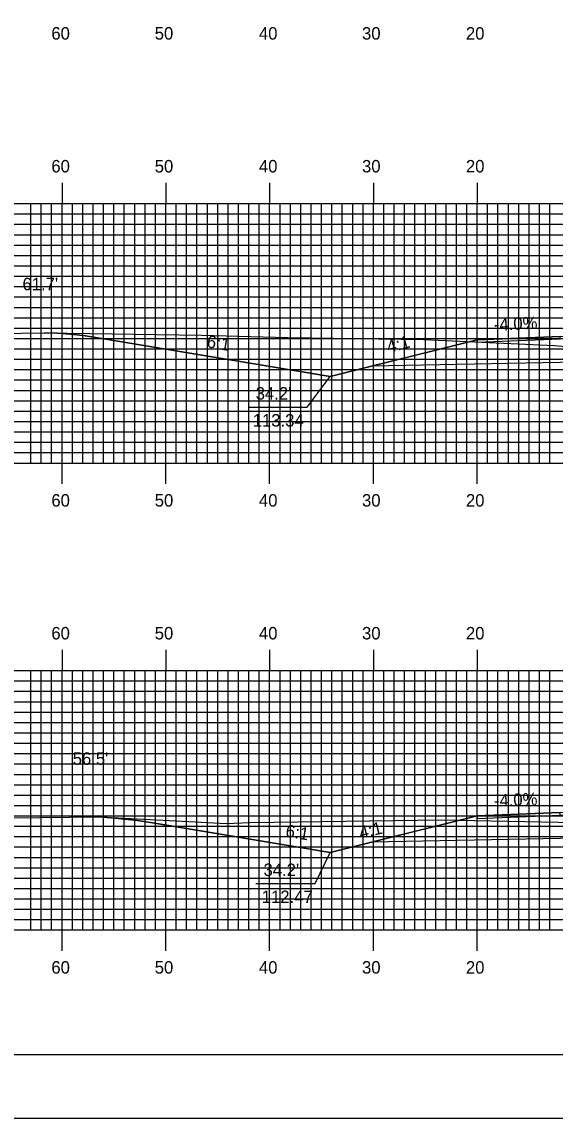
# Model space of a CAD drawing. Extents: x 1780286 to 1780629, y 442591 to 442811.
# Drawn here: x 1780388 to 1780439.4, y 442590.5 to 442696.2 of the extents above; entities that cross this region are included whole.
import ezdxf

# ---------------------------------------------------------------- set-up
doc = ezdxf.new("R2010")
doc.units = 0
for name, color, linetype in [('ANNOTATION', 7, 'Continuous'), ('BORDER', 7, 'Continuous'), ('D_Roadway_Centerline', 7, 'Continuous'), ('D_Roadway_Edge_Shoulder', 7, 'Continuous'), ('D_Roadway_SlopeLines', 7, 'Continuous'), ('D_Roadway_SubGrade', 7, 'Continuous'), ('D_Text_Standard', 7, 'Continuous'), ('H_V ANNOTATION', 7, 'Continuous'), ('MAJOR', 7, 'Continuous'), ('MINOR', 7, 'Continuous'), ('PLOT BOUNDARY', 7, 'Continuous'), ('S_Roadway_Centerline', 7, 'Continuous')]:
    doc.layers.add(name, color=color, linetype=linetype)

msp = doc.modelspace()

# ---------------------------------------------------------------- linework, layer by layer
at = {"layer": 'ANNOTATION'}
for points in [[(1780409.8, 442659.05), (1780415.49, 442659.05), (1780417.69, 442662.01)], [(1780410.55, 442613.15), (1780416.24, 442613.15), (1780417.69, 442616.13)]]:
    msp.add_lwpolyline(points, dxfattribs=at)
at = {"layer": 'BORDER'}
msp.add_lwpolyline([(1780302.27, 442596.67), (1780622.27, 442596.67), (1780622.27, 442806.67), (1780302.27, 442806.67)], close=True, dxfattribs=at)
at = {"layer": 'D_Roadway_Centerline'}
for points in [[(1780390.14, 442666.22), (1780391.39, 442666.18), (1780392.64, 442666.09), (1780393.89, 442665.95), (1780395.14, 442665.77), (1780417.69, 442662.01), (1780421.69, 442663.01), (1780431.87, 442665.55), (1780439.87, 442665.87), (1780451.87, 442666.11), (1780463.87, 442665.87), (1780471.87, 442665.55), (1780482.04, 442663.01), (1780486.04, 442662.01), (1780493.57, 442663.26), (1780494.82, 442663.44), (1780496.07, 442663.55), (1780497.32, 442663.59), (1780498.57, 442663.57)], [(1780395.38, 442619.56), (1780396.63, 442619.48), (1780397.88, 442619.36), (1780399.13, 442619.21), (1780400.38, 442619.02), (1780417.69, 442616.13), (1780421.69, 442617.13), (1780431.87, 442619.68), (1780439.87, 442620), (1780451.87, 442620.24), (1780463.87, 442620), (1780471.87, 442619.68), (1780482.04, 442617.13), (1780486.04, 442616.13), (1780490.6, 442616.89), (1780491.85, 442617.07), (1780493.1, 442617.19), (1780494.35, 442617.24), (1780495.6, 442617.23)]]:
    msp.add_lwpolyline(points, dxfattribs=at)
at = {"layer": 'D_Roadway_Edge_Shoulder'}
for points in [[(1780439.87, 442665.87), (1780431.87, 442665.55), (1780431.87, 442665.3), (1780439.87, 442665.62)], [(1780439.87, 442620), (1780431.87, 442619.68), (1780431.87, 442619.43), (1780439.87, 442619.75)]]:
    msp.add_lwpolyline(points, close=True, dxfattribs=at)
at = {"layer": 'D_Roadway_SlopeLines'}
for points in [[(1780417.69, 442662.01), (1780395.14, 442665.77), (1780393.89, 442665.95), (1780392.64, 442666.09), (1780391.39, 442666.18), (1780390.14, 442666.22)], [(1780431.87, 442665.55), (1780417.69, 442662.01)], [(1780417.69, 442616.13), (1780400.38, 442619.02), (1780399.13, 442619.21), (1780397.88, 442619.36), (1780396.63, 442619.48), (1780395.38, 442619.56)], [(1780431.87, 442619.68), (1780417.69, 442616.13)]]:
    msp.add_lwpolyline(points, dxfattribs=at)
at = {"layer": 'D_Roadway_SubGrade'}
for points in [[(1780439.87, 442663.37), (1780421.69, 442663.01), (1780431.87, 442665.55), (1780431.87, 442665.3), (1780439.87, 442665.62), (1780451.87, 442665.86), (1780463.87, 442665.62), (1780471.87, 442665.3), (1780471.87, 442665.55), (1780482.04, 442663.01), (1780463.87, 442663.37), (1780451.87, 442663.61)], [(1780439.87, 442617.5), (1780421.69, 442617.13), (1780431.87, 442619.68), (1780431.87, 442619.43), (1780439.87, 442619.75), (1780451.87, 442619.99), (1780463.87, 442619.75), (1780471.87, 442619.43), (1780471.87, 442619.68), (1780482.04, 442617.13), (1780463.87, 442617.5), (1780451.87, 442617.74)]]:
    msp.add_lwpolyline(points, close=True, dxfattribs=at)
at = {"layer": 'MAJOR'}
for p, q in [((1780391.87, 442680.67), (1780391.87, 442678.67)), ((1780401.87, 442680.67), (1780401.87, 442678.67)), ((1780411.87, 442680.67), (1780411.87, 442678.67)), ((1780421.87, 442680.67), (1780421.87, 442678.67)), ((1780431.87, 442680.67), (1780431.87, 442678.67)), ((1780311.87, 442678.67), (1780591.87, 442678.67)), ((1780311.87, 442678.67), (1780591.87, 442678.67)), ((1780391.87, 442653.67), (1780391.87, 442678.67)), ((1780401.87, 442653.67), (1780401.87, 442678.67)), ((1780411.87, 442653.67), (1780411.87, 442678.67)), ((1780421.87, 442653.67), (1780421.87, 442678.67)), ((1780431.87, 442653.67), (1780431.87, 442678.67)), ((1780311.87, 442673.67), (1780591.87, 442673.67)), ((1780311.87, 442668.67), (1780591.87, 442668.67)), ((1780311.87, 442663.67), (1780591.87, 442663.67)), ((1780311.87, 442658.67), (1780591.87, 442658.67)), ((1780311.87, 442653.67), (1780591.87, 442653.67)), ((1780311.87, 442653.67), (1780591.87, 442653.67)), ((1780391.87, 442651.66), (1780391.87, 442653.67)), ((1780401.87, 442651.66), (1780401.87, 442653.67)), ((1780411.87, 442651.66), (1780411.87, 442653.67)), ((1780421.87, 442651.66), (1780421.87, 442653.67)), ((1780431.87, 442651.66), (1780431.87, 442653.67)), ((1780391.87, 442635.67), (1780391.87, 442633.67)), ((1780401.87, 442635.67), (1780401.87, 442633.67)), ((1780411.87, 442635.67), (1780411.87, 442633.67)), ((1780421.87, 442635.67), (1780421.87, 442633.67)), ((1780431.87, 442635.67), (1780431.87, 442633.67)), ((1780311.87, 442633.67), (1780591.87, 442633.67)), ((1780311.87, 442633.67), (1780591.87, 442633.67)), ((1780391.87, 442608.67), (1780391.87, 442633.67)), ((1780401.87, 442608.67), (1780401.87, 442633.67)), ((1780411.87, 442608.67), (1780411.87, 442633.67)), ((1780421.87, 442608.67), (1780421.87, 442633.67)), ((1780431.87, 442608.67), (1780431.87, 442633.67)), ((1780311.87, 442628.67), (1780591.87, 442628.67)), ((1780311.87, 442623.67), (1780591.87, 442623.67)), ((1780311.87, 442618.67), (1780591.87, 442618.67)), ((1780311.87, 442613.67), (1780591.87, 442613.67)), ((1780311.87, 442608.67), (1780591.87, 442608.67)), ((1780311.87, 442608.67), (1780591.87, 442608.67)), ((1780391.87, 442606.66), (1780391.87, 442608.67)), ((1780401.87, 442606.66), (1780401.87, 442608.67)), ((1780411.87, 442606.66), (1780411.87, 442608.67)), ((1780421.87, 442606.66), (1780421.87, 442608.67)), ((1780431.87, 442606.66), (1780431.87, 442608.67))]:
    msp.add_line(p, q, dxfattribs=at)
at = {"layer": 'MINOR'}
for p, q in [((1780388.87, 442653.67), (1780388.87, 442678.67)), ((1780389.87, 442653.67), (1780389.87, 442678.67)), ((1780390.87, 442653.67), (1780390.87, 442678.67)), ((1780392.87, 442653.67), (1780392.87, 442678.67)), ((1780393.87, 442653.67), (1780393.87, 442678.67)), ((1780394.87, 442653.67), (1780394.87, 442678.67)), ((1780395.87, 442653.67), (1780395.87, 442678.67)), ((1780396.87, 442653.67), (1780396.87, 442678.67)), ((1780397.87, 442653.67), (1780397.87, 442678.67)), ((1780398.87, 442653.67), (1780398.87, 442678.67)), ((1780399.87, 442653.67), (1780399.87, 442678.67)), ((1780400.87, 442653.67), (1780400.87, 442678.67)), ((1780402.87, 442653.67), (1780402.87, 442678.67)), ((1780403.87, 442653.67), (1780403.87, 442678.67)), ((1780404.87, 442653.67), (1780404.87, 442678.67)), ((1780405.87, 442653.67), (1780405.87, 442678.67)), ((1780406.87, 442653.67), (1780406.87, 442678.67)), ((1780407.87, 442653.67), (1780407.87, 442678.67)), ((1780408.87, 442653.67), (1780408.87, 442678.67)), ((1780409.87, 442653.67), (1780409.87, 442678.67)), ((1780410.87, 442653.67), (1780410.87, 442678.67)), ((1780412.87, 442653.67), (1780412.87, 442678.67)), ((1780413.87, 442653.67), (1780413.87, 442678.67)), ((1780414.87, 442653.67), (1780414.87, 442678.67)), ((1780415.87, 442653.67), (1780415.87, 442678.67)), ((1780416.87, 442653.67), (1780416.87, 442678.67)), ((1780417.87, 442653.67), (1780417.87, 442678.67)), ((1780418.87, 442653.67), (1780418.87, 442678.67)), ((1780419.87, 442653.67), (1780419.87, 442678.67)), ((1780420.87, 442653.67), (1780420.87, 442678.67)), ((1780422.87, 442653.67), (1780422.87, 442678.67)), ((1780423.87, 442653.67), (1780423.87, 442678.67)), ((1780424.87, 442653.67), (1780424.87, 442678.67)), ((1780425.87, 442653.67), (1780425.87, 442678.67)), ((1780426.87, 442653.67), (1780426.87, 442678.67)), ((1780427.87, 442653.67), (1780427.87, 442678.67)), ((1780428.87, 442653.67), (1780428.87, 442678.67)), ((1780429.87, 442653.67), (1780429.87, 442678.67)), ((1780430.87, 442653.67), (1780430.87, 442678.67)), ((1780432.87, 442653.67), (1780432.87, 442678.67)), ((1780433.87, 442653.67), (1780433.87, 442678.67)), ((1780434.87, 442653.67), (1780434.87, 442678.67)), ((1780435.87, 442653.67), (1780435.87, 442678.67)), ((1780436.87, 442653.67), (1780436.87, 442678.67)), ((1780437.87, 442653.67), (1780437.87, 442678.67)), ((1780438.87, 442653.67), (1780438.87, 442678.67)), ((1780311.87, 442677.67), (1780591.87, 442677.67)), ((1780311.87, 442676.67), (1780591.87, 442676.67)), ((1780311.87, 442675.67), (1780591.87, 442675.67)), ((1780311.87, 442674.67), (1780591.87, 442674.67)), ((1780311.87, 442672.67), (1780591.87, 442672.67)), ((1780311.87, 442671.67), (1780591.87, 442671.67)), ((1780311.87, 442670.67), (1780591.87, 442670.67)), ((1780311.87, 442669.67), (1780591.87, 442669.67)), ((1780311.87, 442667.67), (1780591.87, 442667.67)), ((1780311.87, 442666.67), (1780591.87, 442666.67)), ((1780311.87, 442665.67), (1780591.87, 442665.67)), ((1780311.87, 442664.67), (1780591.87, 442664.67)), ((1780311.87, 442662.67), (1780591.87, 442662.67)), ((1780311.87, 442661.67), (1780591.87, 442661.67)), ((1780311.87, 442660.67), (1780591.87, 442660.67)), ((1780311.87, 442659.67), (1780591.87, 442659.67)), ((1780311.87, 442657.67), (1780591.87, 442657.67)), ((1780311.87, 442656.67), (1780591.87, 442656.67)), ((1780311.87, 442655.67), (1780591.87, 442655.67)), ((1780311.87, 442654.67), (1780591.87, 442654.67)), ((1780388.87, 442608.67), (1780388.87, 442633.67)), ((1780389.87, 442608.67), (1780389.87, 442633.67)), ((1780390.87, 442608.67), (1780390.87, 442633.67)), ((1780392.87, 442608.67), (1780392.87, 442633.67)), ((1780393.87, 442608.67), (1780393.87, 442633.67)), ((1780394.87, 442608.67), (1780394.87, 442633.67)), ((1780395.87, 442608.67), (1780395.87, 442633.67)), ((1780396.87, 442608.67), (1780396.87, 442633.67)), ((1780397.87, 442608.67), (1780397.87, 442633.67)), ((1780398.87, 442608.67), (1780398.87, 442633.67)), ((1780399.87, 442608.67), (1780399.87, 442633.67)), ((1780400.87, 442608.67), (1780400.87, 442633.67)), ((1780402.87, 442608.67), (1780402.87, 442633.67)), ((1780403.87, 442608.67), (1780403.87, 442633.67)), ((1780404.87, 442608.67), (1780404.87, 442633.67)), ((1780405.87, 442608.67), (1780405.87, 442633.67)), ((1780406.87, 442608.67), (1780406.87, 442633.67)), ((1780407.87, 442608.67), (1780407.87, 442633.67)), ((1780408.87, 442608.67), (1780408.87, 442633.67)), ((1780409.87, 442608.67), (1780409.87, 442633.67)), ((1780410.87, 442608.67), (1780410.87, 442633.67)), ((1780412.87, 442608.67), (1780412.87, 442633.67)), ((1780413.87, 442608.67), (1780413.87, 442633.67)), ((1780414.87, 442608.67), (1780414.87, 442633.67)), ((1780415.87, 442608.67), (1780415.87, 442633.67)), ((1780416.87, 442608.67), (1780416.87, 442633.67)), ((1780417.87, 442608.67), (1780417.87, 442633.67)), ((1780418.87, 442608.67), (1780418.87, 442633.67)), ((1780419.87, 442608.67), (1780419.87, 442633.67)), ((1780420.87, 442608.67), (1780420.87, 442633.67)), ((1780422.87, 442608.67), (1780422.87, 442633.67)), ((1780423.87, 442608.67), (1780423.87, 442633.67)), ((1780424.87, 442608.67), (1780424.87, 442633.67)), ((1780425.87, 442608.67), (1780425.87, 442633.67)), ((1780426.87, 442608.67), (1780426.87, 442633.67)), ((1780427.87, 442608.67), (1780427.87, 442633.67)), ((1780428.87, 442608.67), (1780428.87, 442633.67)), ((1780429.87, 442608.67), (1780429.87, 442633.67)), ((1780430.87, 442608.67), (1780430.87, 442633.67)), ((1780432.87, 442608.67), (1780432.87, 442633.67)), ((1780433.87, 442608.67), (1780433.87, 442633.67)), ((1780434.87, 442608.67), (1780434.87, 442633.67)), ((1780435.87, 442608.67), (1780435.87, 442633.67)), ((1780436.87, 442608.67), (1780436.87, 442633.67)), ((1780437.87, 442608.67), (1780437.87, 442633.67)), ((1780438.87, 442608.67), (1780438.87, 442633.67)), ((1780311.87, 442632.67), (1780591.87, 442632.67)), ((1780311.87, 442631.67), (1780591.87, 442631.67)), ((1780311.87, 442630.67), (1780591.87, 442630.67)), ((1780311.87, 442629.67), (1780591.87, 442629.67)), ((1780311.87, 442627.67), (1780591.87, 442627.67)), ((1780311.87, 442626.67), (1780591.87, 442626.67)), ((1780311.87, 442625.67), (1780591.87, 442625.67)), ((1780311.87, 442624.67), (1780591.87, 442624.67)), ((1780311.87, 442622.67), (1780591.87, 442622.67)), ((1780311.87, 442621.67), (1780591.87, 442621.67)), ((1780311.87, 442620.67), (1780591.87, 442620.67)), ((1780311.87, 442619.67), (1780591.87, 442619.67)), ((1780311.87, 442617.67), (1780591.87, 442617.67)), ((1780311.87, 442616.67), (1780591.87, 442616.67)), ((1780311.87, 442615.67), (1780591.87, 442615.67)), ((1780311.87, 442614.67), (1780591.87, 442614.67)), ((1780311.87, 442612.67), (1780591.87, 442612.67)), ((1780311.87, 442611.67), (1780591.87, 442611.67)), ((1780311.87, 442610.67), (1780591.87, 442610.67)), ((1780311.87, 442609.67), (1780591.87, 442609.67))]:
    msp.add_line(p, q, dxfattribs=at)
at = {"layer": 'PLOT BOUNDARY'}
msp.add_lwpolyline([(1780286.08, 442590.55), (1780626.08, 442590.55), (1780626.08, 442810.55), (1780286.08, 442810.55)], close=True, dxfattribs=at)
at = {"layer": 'S_Roadway_Centerline'}
for points in [[(1780311.87, 442669.26), (1780313.82, 442669.05), (1780317.25, 442668.73), (1780327.63, 442667.81), (1780336.57, 442667.6), (1780344.45, 442667.39), (1780357.65, 442666.97), (1780362.28, 442666.8), (1780381.18, 442666.41), (1780385.56, 442666.15), (1780390.26, 442666.22), (1780405.31, 442666), (1780413.62, 442665.77), (1780426.7, 442665.56), (1780439.31, 442664.98), (1780444.55, 442664.51), (1780449.19, 442664.46), (1780462.56, 442664.28), (1780467.58, 442664.17), (1780471.44, 442664.14), (1780486.05, 442664.03), (1780489.63, 442663.98), (1780509.62, 442663.05)], [(1780386.91, 442619.48), (1780395.43, 442619.57), (1780405.3, 442619.05), (1780407.69, 442618.94), (1780409.95, 442619.02), (1780428.41, 442619.28), (1780433.22, 442619.18), (1780452.65, 442618.8), (1780453.99, 442618.75), (1780455.37, 442618.72), (1780465.44, 442618.15), (1780473.41, 442618), (1780482.26, 442617.65), (1780496.12, 442617.22), (1780505.3, 442616.88)]]:
    msp.add_lwpolyline(points, dxfattribs=at)

# ---------------------------------------------------------------- texts
at = {"layer": 'ANNOTATION'}
for s, rotation, p in [('-4.0%', 2.2906, (1780433.5, 442666.42)), ('6:1', 350.5377, (1780405.75, 442664.83)), ('4:1', 14.0362, (1780423.32, 442664.28)), ('-4.0%', 2.2906, (1780433.5, 442620.54)), ('6:1', 350.5377, (1780413.34, 442617.67)), ('4:1', 14.0362, (1780420.66, 442617.44))]:
    msp.add_text(s, height=1.2, rotation=rotation, dxfattribs=at).set_placement(p)
for s, p in [("34.2'", (1780410.53, 442659.78)), ('113.34', (1780410.24, 442657.18)), ("34.2'", (1780411.28, 442613.87)), ('112.47', (1780411.11, 442611.27))]:
    msp.add_text(s, height=1.2, dxfattribs=at).set_placement(p)
at = {"layer": 'D_Text_Standard'}
for s, p in [("61.7'", (1780388.06, 442670.32)), ("56.5'", (1780392.9, 442624.59))]:
    msp.add_text(s, height=1.2, dxfattribs=at).set_placement(p)
at = {"layer": 'H_V ANNOTATION'}
for s, p in [('60', (1780390.84, 442694.47)), ('50', (1780400.8, 442694.47)), ('40', (1780410.84, 442694.47)), ('30', (1780420.77, 442694.47)), ('20', (1780430.78, 442694.47)), ('60', (1780390.84, 442681.67)), ('50', (1780400.8, 442681.67)), ('40', (1780410.84, 442681.67)), ('30', (1780420.77, 442681.67)), ('20', (1780430.78, 442681.67)), ('60', (1780390.84, 442649.47)), ('50', (1780400.8, 442649.47)), ('40', (1780410.84, 442649.47)), ('30', (1780420.77, 442649.47)), ('20', (1780430.78, 442649.47)), ('60', (1780390.84, 442636.67)), ('50', (1780400.8, 442636.67)), ('40', (1780410.84, 442636.67)), ('30', (1780420.77, 442636.67)), ('20', (1780430.78, 442636.67)), ('60', (1780390.84, 442604.47)), ('50', (1780400.8, 442604.47)), ('40', (1780410.84, 442604.47)), ('30', (1780420.77, 442604.47)), ('20', (1780430.78, 442604.47))]:
    msp.add_text(s, height=1.2, dxfattribs=at).set_placement(p)

doc.saveas('drawing.dxf')
